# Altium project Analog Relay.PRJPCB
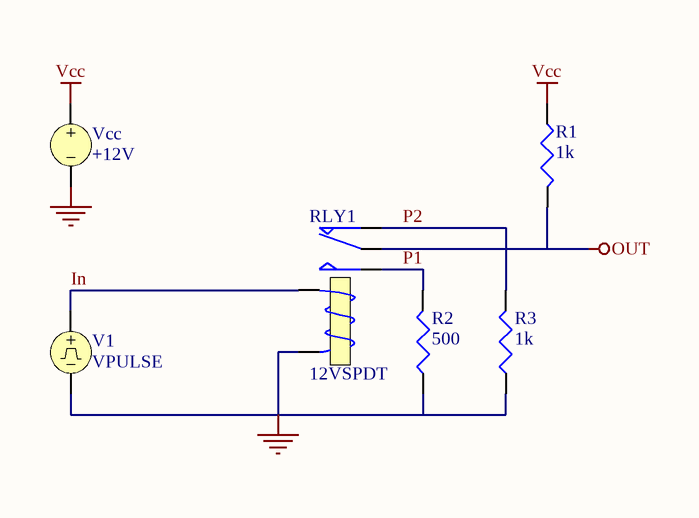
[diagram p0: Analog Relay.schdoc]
1 sheet, 6 parts. Net scope: global (net labels, ports and power ports of the same name join across sheets).

## Sheet Analog Relay.schdoc: Analog Relay
size A4; Organization: Altium Limited; Address1: L3, 12a Rodborough Rd; Address2: Frenchs Forest; Address3: NSW; Address4: Australia 2086; DocumentNumber: 1; SheetNumber: 1; SheetTotal: 1

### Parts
R1  1k
R2  500
R3  1k
RLY1  12VSPDT
V1  VPULSE
Vcc  +12V

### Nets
GND: R2.2(BOT) R3.2(BOT) RLY1.5 V1.2 Vcc.2
OUT: R1.1(TOP) RLY1.1
Vcc: R1.2(BOT) Vcc.1
In: RLY1.4 V1.1
P1: R2.1(TOP) RLY1.3
P2: R3.1(TOP) RLY1.2

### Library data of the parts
R1-R3 = RES: Resistor
RLY1 = 12VSPDT: SPDT Relay
V1 = VPULSE: Pulse Voltage Source
Vcc = VSRC: Voltage Source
